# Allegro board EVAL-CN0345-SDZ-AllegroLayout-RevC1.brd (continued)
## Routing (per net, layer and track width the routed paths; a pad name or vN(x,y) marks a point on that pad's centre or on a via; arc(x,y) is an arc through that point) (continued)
GPIO2: length 43.5
  TOP w0.305: v1(127.64,13.97) 120.65,13.97 113.03,6.35 111.76,6.35 108.27,9.84 R21.2 ; P22.44 139.51,20.45 v1(140.02,20.95)
  BOTTOM w0.305: v1(127.64,13.97) 127.64,15.01 130.09,17.46 130.18,17.46 130.18,17.48 130.48,17.78 132.4,17.78 135.06,20.44 139.51,20.44 v1(140.02,20.95)
GPIO3: length 33.4
  TOP w0.305: v1(108.04,7.62) R19.2 ; P22.77 129.04,20.45 127.64,19.05 127.64,16.51 126.37,15.24 118.75,15.24 113.67,10.16 v1(111.44,10.16)
  BOTTOM w0.305: v1(108.04,7.62) 108.9,7.62 v1(111.44,10.16)
GPIO4: length 42.2
  TOP w0.305: v1(126.37,13.14) 121.73,13.14 113.67,5.08 107.38,5.08 107.06,5.4 R18.2 ; P22.45 140.08,19.86 v1(140.11,19.89)
  BOTTOM w0.305: v1(126.37,13.14) 127.85,13.14 128.59,13.88 128.59,14.92 130.81,17.14 132.72,17.14 135.42,19.85 139.35,19.85 139.38,19.89 v1(140.11,19.89)
GPIO5: length 35.1
  TOP w0.305: v1(108.27,3.17) R17.2 ; v1(112.71,7.62) 113.03,7.62 120.02,14.61 126.68,14.61 128.27,16.19 128.27,18.8 129.32,19.85 P22.76
  BOTTOM w0.305: v1(112.71,7.62) v1(108.27,3.17)
IN0A: length 14.4
  TOP w0.305: U2.19 47.27,25.04 46.36,24.13 43.82,24.13 41.12,26.83 39.26,26.83 38.2,27.89 C9.2 R9.2
IN0B: length 14.3
  TOP w0.305: U2.11 46.62,33.24 46.63,33.26 46.63,33.81 46.62,33.82 46.62,34.03 46.36,34.29 44.77,34.29 41.75,31.27 39.26,31.27 38.2,30.21 C8.2
  TOP w0.381: C8.2 R8.2
IN1A: length 15.2
  TOP w0.305: R10.2 C10.2 38.2,25.67 39.26,24.61 41.75,24.61 43.02,23.34 46.83,23.34 47.92,24.42 U2.20
IN1B: length 14.7
  TOP w0.305: C7.2 38.2,32.44 39.26,33.5 41.58,33.5 43.17,35.08 46.36,35.08 47.27,34.17 U2.10
  TOP w0.381: R7.2 C7.2
IN2A: length 16
  TOP w0.305: U2.21 48.57,23.8 47.15,22.38 39.26,22.38 38.2,23.44 C11.2 R11.2
IN2B: length 15.4
  TOP w0.305: U2.9 47.92,34.79 46.99,35.72 39.26,35.72 38.2,34.66 C6.2
  TOP w0.381: C6.2 R6.2
IN3A: length 17.8
  TOP w0.305: U2.22 49.22,23.41 45.97,20.16 39.26,20.16 38.2,21.22 C12.2 R12.2
IN3B: length 17.3
  TOP w0.305: C5.2 38.2,36.88 39.26,37.94 46.04,37.94 48.57,35.41 U2.8
  TOP w0.381: C5.2 R5.2
IN4A: length 19.5
  TOP w0.305: U2.23 49.87,23.2 44.61,17.94 39.26,17.94 38.2,19 C13.2 R13.2
IN4B: length 19.1
  TOP w0.305: C4.2 38.2,39.1 39.26,40.16 44.93,40.16 49.22,35.87 U2.7
  TOP w0.381: R4.2 C4.2
IN5A: length 21.3
  TOP w0.305: U2.24 50.52,22.9 43.34,15.72 39.26,15.72 38.2,16.78 C14.2 R14.2
IN5B: length 21.1
  TOP w0.305: U2.6 49.87,36.49 43.97,42.39 39.26,42.39 38.2,41.33 C3.2
  TOP w0.381: C3.2 R3.2
IN6A: length 23.2
  TOP w0.305: R15.2 C15.2 38.2,14.55 39.26,13.49 42.39,13.49 51.17,22.28 U2.25
IN6B: length 23
  TOP w0.305: U2.5 50.52,37.11 43.02,44.61 39.26,44.61 38.2,43.55 C2.2
  TOP w0.381: C2.2 R2.2
IN7A: length 25.1
  TOP w0.305: U2.26 51.82,21.66 41.43,11.27 39.26,11.27 38.2,12.33 C16.2 R16.2
IN7B: length 24.9
  TOP w0.305: U2.4 51.17,37.73 42.07,46.83 39.26,46.83 38.2,45.77 C1.2
  TOP w0.381: R1.2 C1.2
IN+: length 31
  TOP w0.305: U1.3 100.63,22.86 100.32,22.54
  TOP w0.635: 100.32,22.54 97.47,22.54 IN+.1 93.35,24.13 92.71,23.49 C28.1 88.68,23.49 C30.2 88.58,25.3 R32.2 ; R27.2 v1(90.17,32.54)
  BOTTOM w0.635: IN+.1 90.17,29.84 v1(90.17,32.54)
IN-: length 14.9
  TOP w0.635: IN-.1 88.48,17.68 R33.2 88.48,21.59 C30.1 88.68,21.59 C29.2 92.71,21.59 93.66,20.64 R29.1
MUX_ADDR0: length 79
  TOP w0.305: U2.17 v1(45.97,24.89)
  TOP w0.381: R19.1 R71.2 102.24,7.05 101.7,6.51 91.6,6.51 89.54,4.45 MUX_0.1 84.33,7.43 70.93,7.43 66.97,3.47 57.8,3.47 P6.2
  BOTTOM w0.305: P6.2 51.12,10.16 51.12,10.52 51.15,10.55 51.15,11.04 51.12,11.07 51.12,12.38 47.63,15.88 47.63,23.23 v1(45.97,24.89)
MUX_ADDR1: length 86.8
  TOP w0.305: U2.16 v1(45.32,27.68) ; R18.1 R70.2
  TOP w0.381: P5.2 51.12,6.35 51.12,3.08 51.5,2.7 67.47,2.7 71.44,6.67 77.79,6.67 MUX_1.1 81.6,2.86 91.44,2.86 92.87,4.29 101.82,4.29 102.24,4.7 R70.2
  BOTTOM w0.305: P5.2 47.31,10.16 47.31,10.52 47.34,10.55 47.34,11.04 47.31,11.07 47.31,13.65 46.04,14.92 46.04,21.91 45.25,22.7 45.25,25.19 45.32,25.26 v1(45.32,27.68)
MUX_ADDR2: length 86.6
  TOP w0.305: U2.15 44.67,25.46 v1(44.13,24.92)
  TOP w0.381: P4.2 47.31,6.35 47.31,2.44 47.69,2.06 68.26,2.06 70.64,4.45 MUX_2.1 74.61,4.45 77.47,1.59 101.35,1.59 102.24,2.48 R69.2 R17.1
  BOTTOM w0.305: v1(44.13,24.92) 44.13,21.27 43.47,20.61 43.47,10.19 P4.2
MUX_EN: length 26
  TOP w0.305: U2.18 v1(46.62,27.68)
  BOTTOM w0.305: P26.2 46.67,41.91 47.63,40.96 47.63,30.8 46.62,29.79 v1(46.62,27.68)
N15VA: length 16.9
  TOP w0.305: v1(67,32.23) 66.72,31.95 U3.6
  TOP w0.508: 71.76,50.42 P21.3 ; P21.3 70.42,51.75 ; P21.3 71.76,53.09
  L3_POWER w0.508: 61.91,17.78 P12.2 ; P12.2 63.18,16.51 ; P12.2 63.18,19.05 ; P7.2 58.74,19.05 ; P7.2 60.01,17.78 ; P7.2 58.74,16.51 ; P21.3 71.76,53.09 ; P21.3 71.76,50.42 ; P21.3 70.42,51.75
PD: length 90.7
  TOP w0.305: P23.3 92.71,44.77 v1(96.52,48.58) ; v1(127.32,12.38) v1(123.19,12.38) ; v1(140.02,17.78) 139.75,18.05 P22.48
  BOTTOM w0.305: v1(127.32,12.38) 128.27,12.38 130.49,14.61 133.03,14.61 136.21,17.78 v1(140.02,17.78) ; v1(96.52,48.58) 117.49,48.58 120.02,46.05 120.02,37.78 120.65,37.15 120.65,32.38 119.38,31.11 119.38,16.19 v1(123.19,12.38)
SCLK: length 20.1
  TOP w0.305: U16.4 121.3,33.03 SCLK.1 111.13,22.86 U1.8
SDI: length 18
  TOP w0.305: P18.2 115.57,34.61 115.57,31.75 SDI.1 110.81,26.99 110.81,24.13 110.04,23.36 U1.9
SDO: length 30.3
  TOP w0.305: P22.91 126.8,28.85 125.91,27.97 124.24,27.97 124.22,27.94 121.92,27.94 121.6,27.62 120.33,27.62 SDO.1 110.99,22.36 U1.7
SDP_3P3V: length 51.7
  TOP w0.305: U12.3 123.22,7.65 122.87,7.3 v1(122.87,6.99) 122.87,6.34 122.57,6.03 121.67,6.03 R65.2 ; U12.8 127.29,9.09 127.32,9.12 127.32,9.84
  TOP w0.381: P22.116 131.23,43.85 130.87,43.5
  TOP w0.635: 127.32,9.84 125.57,11.59 v1(124.62,11.59) ; 130.87,43.5 129.86,43.5 v1(129.54,43.18)
  BOTTOM w0.305: v1(122.87,6.99) 122.87,10.16 123.51,10.8 123.83,10.8 v1(124.62,11.59)
  BOTTOM w0.635: v1(124.62,11.59) 124.62,12.48 124.78,12.64 124.78,13.97 127.32,16.51 127.32,23.16 129.98,25.82 129.98,27.5 129.54,27.94 v1(129.54,43.18)
SPORT_DT0: length 22.4
  TOP w0.305: P18.3 120.14,35.56 120.78,34.92 v1(128.59,34.92) ; v1(128.78,26.67) 129.16,27.05 P22.88
  BOTTOM w0.305: v1(128.59,34.92) 128.59,34.2 128.78,34.01 v1(128.78,26.67)
SPORT_RFS: length 10.7
  TOP w0.305: P22.90 126.99,28.25 126.15,27.41 124.47,27.41 123.75,26.68 U15.4
SPORT_RSCLK: length 22.3
  TOP w0.305: U14.4 122.37,20.33 122.35,20.32 v1(121.29,20.32) ; P22.92 126.61,29.45 125.73,28.57 v1(121.29,28.57)
  BOTTOM w0.305: v1(121.29,28.57) 120.65,27.94 120.65,20.95 v1(121.29,20.32)
SPORT_TSCLK: length 22
  TOP w0.305: P22.87 129.64,26.45 128.91,25.72 v1(127.95,25.72) 126.68,24.45 126.68,20.95 125.49,19.76 125.3,19.76 125.23,19.68 U14.2 ; U16.1 125.28,31.74 125.3,31.75 v1(127.64,31.75)
  BOTTOM w0.305: v1(127.95,25.72) 127.95,30.71 127.64,31.03 v1(127.64,31.75)
SW0: length 41.8
  TOP w0.305: R8.1 25.4,30.16 25.08,30.48 S1.8 22.23,30.48 20.96,31.75 13.97,31.75 6.35,39.37 6.35,46.62 P1.8
SW1: length 42.9
  TOP w0.305: R7.1 25.72,32.38 25.08,33.02 S1.7 22.23,33.02 20.96,34.29 13.97,34.29 7.62,40.64 7.62,48.85 P1.7
SW2: length 44.4
  TOP w0.305: R6.1 25.08,34.61 S1.6 22.23,35.56 20.96,36.83 13.34,36.83 8.89,41.27 8.89,51.08 P1.6
SW3: length 45.8
  TOP w0.305: R5.1 27.94,36.83 26.67,38.1 S1.5 22.23,38.1 20.96,39.37 12.7,39.37 10.16,41.91 10.16,53.31 P1.5
SW4: length 46.9
  TOP w0.305: P1.4 11.43,55.54 11.43,43.18 12.7,41.91 20.96,41.91 22.23,40.64 S1.4 26.67,40.64 28.26,39.05 R4.1
SW5: length 47.6
  TOP w0.305: P1.3 12.7,57.77 12.7,45.09 13.34,44.45 20.96,44.45 22.23,43.18 S1.3 27.31,43.18 29.21,41.27 R3.1
SW6: length 43.7
  TOP w0.305: R2.1 30.16,43.5 27.94,45.72 S1.2 23.18,45.72 20.96,47.94 20.96,53.01 P1.2
SW7: length 44.2
  TOP w0.305: P1.1 24.13,53.34 S1.1 27.94,48.26 30.48,45.72 R1.1
UNNAMED_1_AD7982V2_I124_INNEG: length 5.5
  TOP w0.305: R30.1 99.7,20.68 100.28,21.26 100.32,21.26 101.42,22.36 U1.4
  TOP w0.635: R29.2 R30.1
UNNAMED_1_AD7982V2_I124_VDD: length 19.1
  TOP w0.305: C32.2 100.88,23.36 U1.2
  TOP w1.016: C32.2 99.34,23.91 v1(95.28,27.97)
  BOTTOM w1.016: 96.2,37.46 96.2,33.34 95.28,32.42 v1(95.28,27.97)
UNNAMED_1_AD7982V2_I124_VIO: length 13.3
  TOP w0.305: 107.73,25.15 107.79,25.09 107.79,24.19 107.45,23.86 U1.10
  TOP w0.381: C33.1 107.73,25.15
  TOP w0.635: C33.1 107.73,27.05 107.53,27.25 107.53,33.55 P17.2
UNNAMED_1_AD8251_I135_: length 7.9
  TOP w0.305: 64.26,26.67 64.32,26.72 U3.1
  TOP w0.635: R23.1 59.37,27.94 PGIA-.1 64.26,26.67
UNNAMED_1_AD8251_I135__1: length 7.8
  TOP w0.305: 64.26,31.11 64.32,31.06 U3.10
  TOP w0.635: 64.26,31.11 PGIA+.1 59.69,30.16 R24.1
UNNAMED_1_AD8251_I135__2: length 9.2
  TOP w0.305: C23.1 65.41,25.24 65.72,25.56 U3.3
  TOP w1.016: C23.1 C22.1 65.41,20.18 65.72,19.86 P12.1
UNNAMED_1_AD8251_I135__3: length 10.4
  TOP w0.305: U3.8 65.72,32.38 65.41,32.7
  TOP w0.635: C19.2 65.41,33.66 65.41,32.7
  TOP w1.016: P13.2 C20.2 C19.2
UNNAMED_1_AD8251_I135_OUT: length 3.8
  TOP w0.305: U3.7 66.22,30.15 66.53,29.84 67.31,29.84
  TOP w0.635: R26.1 67.31,29.84
UNNAMED_1_AD8475V2_I91_NEGIN04X: length 8.4
  TOP w0.305: R28.2 74.51,26.14 76.84,23.81 76.84,23.49 77.97,22.36 U5.2
UNNAMED_1_AD8475V2_I91_NEGIN08X: length 2.7
  TOP w0.305: U5.1 79.1,21.86 78.32,21.08 C25.2
UNNAMED_1_AD8475V2_I91_NEGVS: length 2.9
  TOP w0.305: U5.8 P24.1
UNNAMED_1_AD8475V2_I91_POSIN08X: length 2.6
  TOP w0.305: C25.1 76.62,20.84 75.6,21.86 U5.10
UNNAMED_1_AD8475V2_I91_POSVS: length 14.8
  TOP w0.305: U5.3 78.35,22.86 77.61,23.61 77.61,24.25 77.15,24.7 C26.2
  TOP w0.635: P15.2 75.88,32.7 75.88,26.14 76.52,25.5 C26.2
UNNAMED_1_AD8475V2_I91_VOCM: length 7
  TOP w0.305: VOCM.1 81.53,23.18 81.35,23.36 U5.4 78.56,23.36 78.32,23.6 78.32,24.03 79.38,25.08 R68.1
UNNAMED_1_ADA48051_I112_: length 18.6
  TOP w0.635: U4.4 85.09,39.05 84.61,39.53 84.61,41.12 83.82,41.91 v1(77.79,41.91) 76.2,41.91 75.41,41.12 75.41,40.43 RN1.2 RN1.1 ; RN1.13 v1(77.79,44.13)
  BOTTOM w0.635: v1(77.79,44.13) v1(77.79,41.91)
UNNAMED_1_ADA48051_I112__1: length 13.9
  TOP w0.635: RN1.12 RN1.11 RN1.10 81.6,44.12 81.9,43.81 85.73,43.81 88.19,41.35 U4.3
UNNAMED_1_ADA48051_I112__2: length 10.6
  TOP w0.635: U4.2 89.22,38.1 89.67,38.55 89.68,38.56 89.68,42.08 UNK-VS.1
  TOP w1.016: UNK-VS.1 P14.1
UNNAMED_1_ADA48051_I112__3: length 5.8
  TOP w0.635: U4.6 85.41,37.15 84.96,36.7 84.96,35.16 C21.1 83.5,34.92 82.87,34.29 P11.2
UNNAMED_1_ADA48051_I112_DISABLE: length 9
  TOP w0.635: U4.5 v1(84.77,38.1)
  BOTTOM w0.635: v1(84.77,38.1) P23.2
UNNAMED_1_ADA48051_I112_VOUT: length 22.3
  TOP w0.635: R27.1 89.85,37.15 U4.1 87.57,37.15 87,37.73 87,40.64 84.77,42.86 76.5,42.86 75.25,44.12 RN1.15 RN1.16
UNNAMED_1_ADG1207_I45_DA: length 3.9
  TOP w0.381: U2.28 53.12,27.4 53.66,27.94 R23.2
UNNAMED_1_ADG1207_I45_DB: length 4.7
  TOP w0.381: R24.2 53.33,30.16 52.47,31.02 U2.2
UNNAMED_1_ADG1207_I45_VDD: length 9.2
  TOP w0.381: C18.1 53.12,33.72 53.12,33.71 U2.1
  TOP w1.016: C18.1 53.12,39.88 53.34,40.09 P8.2
UNNAMED_1_ADG1207_I45_VSS: length 10.7
  TOP w0.305: U2.27 52.47,25.32 52.81,24.98 52.81,23.81 C17.1
  TOP w0.635: P7.1 52.81,21.17 52.81,23.81
UNNAMED_1_CAP_I95_N2: length 13.6
  TOP w0.635: R68.2 79.38,27.77 80.28,28.68 C27.2 81.34,28.68 81.56,28.89 R31.2 R34.1
UNNAMED_1_CN9P_I241_N1: length 35.7
  TOP w0.305: P25.1 5.72,38.73 5.72,37.46 15.24,27.94 R9.1
UNNAMED_1_CN9P_I241_N2: length 34.4
  TOP w0.305: R10.1 15.23,25.72 P25.2
UNNAMED_1_CN9P_I241_N3: length 33.9
  TOP w0.305: R11.1 13.96,23.49 P25.3
UNNAMED_1_CN9P_I241_N4: length 33.4
  TOP w0.305: P25.4 12.68,21.27 R12.1
UNNAMED_1_CN9P_I241_N5: length 32.8
  TOP w0.305: R13.1 11.4,19.05 P25.5
UNNAMED_1_CN9P_I241_N6: length 32.3
  TOP w0.305: P25.6 10.12,16.83 R14.1
UNNAMED_1_CN9P_I241_N7: length 31.8
  TOP w0.305: P25.7 8.85,14.61 R15.1
UNNAMED_1_CN9P_I241_N8: length 31.2
  TOP w0.305: R16.1 7.57,12.38 P25.8
UNNAMED_1_RES_I104_N1: length 27.4
  TOP w0.305: U5.6 74.25,23.86 73.98,24.13 71.12,24.13 70.8,23.81 70.8,18.08 71.11,17.78 79.69,17.78 81.6,19.68 R33.1
UNNAMED_1_RES_I109_N1: length 7.8
  TOP w0.305: U5.5 80.56,23.86 82.1,25.4 R32.1
UNNAMED_1_RES_I214_N2: length 4.5
  TOP w0.635: R20.2 74.35,36.73 75.19,37.57 75.19,37.62 76.52,38.95 RN1.3
UNNAMED_1_RES_I215_N2: length 2.5
  TOP w0.635: RN1.9 82.87,46.79 82.77,46.89 R25.2
UNNAMED_1_RES_I218_N1: length 19.4
  TOP w0.635: R67.1 88.9,31.11 87.63,32.38 81.6,32.38 80.01,33.97 80.01,37.46 79.06,38.42 RN1.5
UNNAMED_1_RESNET16P8R_I207_N1: length 1.3
  TOP w0.635: RN1.7 RN1.8
UNNAMED_1_RESNET16P8R_I208_N1: length 11.2
  TOP w0.635: RN1.14 v1(76.52,46.99) ; v1(77.79,39.05) RN1.4
  BOTTOM w0.635: v1(76.52,46.99) 76.52,40.32 v1(77.79,39.05)
UNNAMED_2_AD8541ART_I251__1: length 3.7
  TOP w0.508: U9.1 102.83,32.66 101.96,32.66 101.6,33.02 101.6,33.62 100.61,34.61 U9.4
UNNAMED_2_ADP121_I85_EN: length 3.5
  TOP w0.635: U11.3 89.54,69.21 89.64,69.32 91.61,69.32
UNNAMED_2_ADP5070_I245_COMP1: length 3.1
  TOP w0.305: 75.57,84.46 75.57,83.87 74.02,82.33 U6.6
UNNAMED_2_ADP5070_I245_COMP2: length 3.4
  TOP w0.305: 70.49,84.46 70.49,83.5 70.8,83.19 71.44,83.19 72.03,82.6 U6.10
UNNAMED_2_ADP5070_I245_EN1: length 8.3
  TOP w0.305: R39.2 R37.2 74.61,83.82 73.53,82.73 U6.7
UNNAMED_2_ADP5070_I245_EN2: length 8.3
  TOP w0.305: U6.9 72.52,83 73.34,83.82 73.34,87 73.03,87.31 R38.2 R41.1
UNNAMED_2_ADP5070_I245_FB1: length 4.3
  TOP w0.305: U6.5 76.09,81.01 76.45,80.65 R52.1 77.25,81.5 77.15,81.6 R44.2
UNNAMED_2_ADP5070_I245_FB2: length 5
  TOP w0.305: U6.11 70.53,81.01 70.17,81.37 70.17,82.3 69.6,82.87 R47.1 R49.1
UNNAMED_2_ADP5070_I245_PVIN1: length 24.5
  TOP w0.635: 63.5,78.42 63.5,85.09 67.95,89.54 R41.2 71.44,91.12 71.76,91.44 75.57,91.44 76.2,90.81 R39.1
UNNAMED_2_ADP5070_I245_SW2: length 1.5
  TOP w0.305: U6.18 73.03,76.52
UNNAMED_2_ADP5070_I245_VREF: length 4.6
  TOP w0.305: U6.12 70.05,80.51 69.91,80.65 69.43,80.65 69.1,80.98 C48.1 69.1,81.1 67.63,82.58 R47.2
UNNAMED_2_ADP5070_I245_VREG: length 2.2
  TOP w0.305: C36.2 69.88,79.51 U6.14
UNNAMED_2_ADP7104_I106_EN: length 4.5
  TOP w0.305: R43.2 91.12,86.36 ; 91.12,86.36 91.12,87.69 91.38,87.95 R48.2 ; 91.12,86.36 91.64,85.84 U7.5
UNNAMED_2_ADP7104_I106_PG: length 2
  TOP w0.305: R54.2 90.87,84.77 90.94,84.84 U7.7
UNNAMED_2_ADP7104_I106_SENSE: length 8.1
  TOP w0.305: R54.1 v1(88.9,84.14)
  BOTTOM w0.305: v1(88.9,84.14) 89.76,83.27 94.93,83.27 95.16,83.5 v1(95.89,83.5)
UNNAMED_2_ADP7104_I106_VIN: length 5.7
  TOP w0.305: R43.1 87.95,86.36 87.63,86.04 87.63,83.3 88.16,82.77 R42.2
UNNAMED_2_ADR43X_I253_COMP: length 3.5
  TOP w0.635: R40.1 101.28,46.14 U8.7
UNNAMED_2_ADR43X_I253_VOUT: length 2.9
  TOP w0.635: U8.6 C39.2
UNNAMED_2_CAP_I115_N1: length 2.2
  TOP w1.016: C37.1 R40.2
UNNAMED_2_CAP_I216_N2: length 17.9
  TOP w0.381: R52.2 v1(80.01,80.65)
  BOTTOM w0.381: v1(80.01,80.65) v1(80.01,63.82)
UNNAMED_2_CAP_I221_N1: length 1.6
  TOP w0.305: R45.2 C46.1
UNNAMED_2_CAP_I228_N1: length 22.7
  TOP w0.381: R49.2 v1(66.68,84.46)
  BOTTOM w0.381: v1(64.77,63.5) 64.77,82.55 v1(66.68,84.46)
UNNAMED_2_CAP_I234_N1: length 1.6
  TOP w0.305: R46.2 C47.1
UNNAMED_2_CAP_I257_N2: length 6.4
  TOP w0.508: UNK+15V.1 85.09,57.47 ; UNK+15V.1 85.09,54.29 ; UNK+15V.1 83.5,55.88 ; UNK+15V.1 86.68,55.88
UNNAMED_2_CAP_I258_N2: length 6.4
  TOP w0.508: UNK-15V.1 63.18,55.88 ; UNK-15V.1 61.6,54.29 ; UNK-15V.1 61.6,57.47 ; UNK-15V.1 60.01,55.88
UNNAMED_2_CN2P_I119_N1: length 54.7
  TOP w2.54: P3.1 103.51,84.77 107.21,81.07 107.21,41.78 105.41,39.98 P2.3
UNNAMED_2_DIOLED_I248_P: length 5.7
  TOP w0.508: POWER.A R35.1
UNNAMED_3_CMOSNC7S04_I15_Y: length 19.1
  TOP w0.305: v1(127.83,33.02) 127.11,33.02 126.47,32.38 U16.2 ; U13.4 122.53,40.92 122.56,40.95 122.56,41.59 122.87,41.91 v1(127.32,41.91)
  BOTTOM w0.305: v1(127.32,41.91) 128.27,40.96 128.27,36.51 127.64,35.88 127.64,33.97 127.83,33.78 v1(127.83,33.02)
UNNAMED_3_CN120PV4_I1_EEPROMA0: length 22.7
  TOP w0.305: v1(124.14,9.53) 124.14,9.12 124.2,9.06 U12.1 122.39,8.65 121.59,9.45 R64.2 ; P22.56 v1(140.01,13.25)
  BOTTOM w0.305: 124.65,10.04 v1(124.14,9.53)
  BOTTOM w0.381: v1(140.01,13.25) 131.04,13.25 127.83,10.04 124.65,10.04
UNNAMED_3_CN120PV4_I1_SCL0: length 19.6
  TOP w0.305: v1(129.22,18.73) 129.22,8.57 128.3,7.65 127.3,7.65 U12.6 ; P22.79 129.6,21.65 v1(129.22,22.03)
  BOTTOM w0.305: v1(129.22,22.03) v1(129.22,18.73)
UNNAMED_3_CN120PV4_I1_SDA0: length 20.3
  TOP w0.305: U12.5 128.75,7.15 130.18,8.57 v1(130.18,19.05) ; v1(130.18,22.6) 130.52,22.25 P22.80
  BOTTOM w0.305: v1(130.18,22.6) v1(130.18,19.05)
UNNAMED_3_IC24XX32A_I2_A1: length 4.9
  TOP w0.305: U12.2 122.94,8.15 122.39,7.6 R65.1 R66.2
VREF: length 8.4
  TOP w0.508: 99.7,27.3 VREF.1
  TOP w0.635: VREF.1 101.75,28.89 101.85,28.99 R53.2
  TOP w1.016: VREF.1 97.47,28.89 96.52,29.84

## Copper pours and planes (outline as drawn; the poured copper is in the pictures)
2.5VA on TOP (solid shape): outline of 98 points within 88.9,53.02 93.98,60.01
2.5VA on BOTTOM (solid shape): 94.93,56.83 94.93,47.94 96.52,46.35 96.52,42.55 97.16,41.91 97.16,39.37 94.93,39.37 94.93,43.18 91.44,46.67 91.44,49.21 88.9,51.75 88.9,57.78 93.98,57.78
5VA on TOP (solid shape): outline of 94 points within 94.93,60.96 99.38,78.42
5VA on L3_POWER: 75.88,28.57 75.88,38.73 80.96,38.73 94.93,52.7 94.93,64.45 95.89,65.41 98.74,65.41 100.65,63.5 129.54,63.5 132.72,60.32 132.72,50.8 135.89,47.62 140.44,47.62 140.44,44.13 133.99,44.13 129.86,48.26 129.86,57.78 127.64,60.01 112.71,60.01 109.22,56.52 109.22,53.34 108.27,52.39 102.24,52.39 97.16,47.31 97.16,34.92 99.06,33.02 99.06,30.16 96.2,30.16 90.81,35.56 88.58,35.56 81.6,28.57
AGND on TOP: 140.97,94.62 0.95,94.62 0.95,0.64 140.97,0.64 ; 4 cut-outs
AGND on BOTTOM: 140.65,93.98 0.95,93.98 0.95,1.27 140.65,1.27
AGND on L2_GND: 1.27,1.27 1.27,93.98 140.44,93.98 140.44,1.27 ; 2 cut-outs
AGND on L3_POWER: 1.27,1.27 1.27,93.98 140.44,93.98 140.44,1.27 ; 2 cut-outs
P15VA on TOP (solid shape): 102.24,58.74 102.24,55 101.99,55 101.99,52.39 100.57,52.39 100.57,55 100.33,55 100.33,58.1 100.01,58.42 98.43,58.42 97.16,57.15 97.16,51.44 94.93,49.21 76.2,49.21 75.57,49.85 75.57,50.55 78.04,50.55 78.04,52.96 75.57,52.96 75.57,53.66 78.42,53.66 78.74,53.98 78.74,57.09 81.03,57.09 81.6,56.52 81.6,53.34 83.19,51.75 93.35,51.75 94.62,53.02 94.62,58.42 96.2,60.01 100.97,60.01
P15VA on BOTTOM (solid shape): outline of 208 points within 50.8,41.91 78.74,53.98
VIN on TOP (solid shape): 87,89.85 87,80.96 84.46,80.96 84.46,88.27 80.33,92.39 65.72,92.39 60.33,87 56.83,87 56.21,87.62 60.72,87.62 60.72,90.92 57.8,90.92 57.8,87.62 56.21,87.62 55.88,87.95 55.88,91.12 58.74,93.98 82.87,93.98
VIN on TOP (solid shape): outline of 205 points within 39.05,73.34 61.28,91.44
3P3V on TOP (solid shape): outline of 123 points within 107.95,33.66 121.29,66.04
3P3V on L3_POWER: 112.71,58.42 112.71,53.66 120.33,46.04 120.33,13.97 114.62,8.25 34.29,8.25 34.29,3.17 125.41,3.17 127.64,5.4 127.64,46.67 115.89,58.42
N15VA on TOP (solid shape): 69.85,56.52 69.85,54.29 70.49,53.66 72.71,53.66 72.71,52.96 72.4,52.78 72.33,52.81 70.55,51.75 72.33,50.69 72.4,50.73 72.71,50.54 72.71,50.16 71.91,49.37 65.72,49.37 65.72,56.83 69.53,56.83
N15VA on L3_POWER (solid shape): outline of 631 points within 57.15,15.88 73.03,53.98
UNNAMED_2_AD8541ART_I251_ on TOP (solid shape): 103.82,34.61 101.92,34.61 101.92,38.73 103.82,38.73
UNNAMED_2_AD8541ART_I251__1 on TOP (solid shape): 103.82,30.16 101.92,30.16 101.92,33.02 103.82,33.02
UNNAMED_2_ADP121_I85_EN on TOP (solid shape): 94.3,66.99 91.12,66.99 91.12,73.03 94.3,73.03
UNNAMED_2_ADP121_I85_VOUT on TOP (solid shape): 93.66,60.64 90.81,60.64 90.81,61.59 91.12,61.91 91.12,66.36 93.66,66.36
UNNAMED_2_ADP124_I107_EN on TOP (solid shape): 113.03,70.17 113.98,69.22 113.98,69.01 112.04,69.01 112.04,68.17 113.98,68.17 113.98,67.31 113.67,66.99 112.71,66.99 112.71,62.87 110.81,62.87 110.81,72.39 113.03,72.39
UNNAMED_2_ADP124_I107_VOUT1 on TOP (solid shape): 121.29,72.07 121.29,66.68 118.11,66.68 117.79,66.99 116.52,66.99 116.52,68.82 118.47,68.82 118.47,68.9 118.75,68.9 118.75,70.48 117.48,70.48 117.48,73.03 120.33,73.03
UNNAMED_2_ADP5070_I245_INBK on TOP (solid shape): 83.19,79.06 83.19,77.15 77.47,77.15 76.2,78.42 74.93,78.42 74.61,78.74 74.61,79.1 76.13,79.1 76.15,79.12 76.2,79.12 76.47,79.19 76.68,79.38 82.87,79.38
UNNAMED_2_ADP5070_I245_PVIN1 on TOP (solid shape): 71.44,78.42 72.62,78.42 72.62,77.38 72.39,77.15 72.39,74.93 72.07,74.61 65.41,74.61 64.14,75.88 62.13,75.88 62.13,76.15 61.53,76.15 61.53,76.45 61.02,76.45 61.02,76.15 60.43,76.15 60.43,75.88 58.74,75.88 58.74,78.11 59.06,78.42 65.09,78.42 66.04,77.47 69.53,77.47 70.17,78.11 70.17,79.06 71.44,79.06
UNNAMED_2_ADP5070_I245_SW1 on TOP (solid shape): 74.77,78.04 75.95,78.04 77.47,76.52 77.47,76.2 77.79,75.88 83.19,75.88 83.19,72.39 82.55,71.76 79.38,71.76 76.2,74.93 76.2,76.52 75.57,77.15 74.61,77.15 73.98,77.79 73.98,78.42 74.39,78.42
UNNAMED_2_ADP5070_I245_SW2 on TOP (solid shape): 73.34,76.89 73.34,68.26 70.8,68.26 70.8,69.53 70.17,70.17 68.26,70.17 67.95,70.48 67.95,73.34 68.26,73.66 72.07,73.66 72.39,73.98 72.39,74.31 72.68,74.31 72.68,74.68 72.77,74.77 72.77,76.99 73.01,77.23
UNNAMED_2_ADP7104_I106_SENSE on TOP (solid shape): 98.43,84.77 98.43,79.06 95.89,79.06 95.89,82.87 94.77,83.98 94.77,84.93 95.52,84.93 95.7,84.97 95.85,85.09 98.11,85.09
UNNAMED_2_ADP7104_I106_VIN on TOP (solid shape): 92.56,83.98 91.54,82.97 91.49,82.97 91.49,82.92 91.12,82.55 91.12,79.06 87.63,79.06 87.63,83.5 90.17,83.5 90.78,84.11 90.87,84.11 90.87,84.2 91.03,84.37 91.04,84.37 91.1,84.43 92.41,84.43 92.48,84.44 92.54,84.46 92.56,84.46
UNNAMED_2_ADR43X_I253_VOUT on TOP (solid shape): 100.65,44.45 100.97,44.13 102.24,44.13 102.55,43.81 102.55,42.55 100.97,42.55 100.97,39.05 101.28,38.73 101.28,36.83 99.38,36.83 99.38,46.67 100.65,46.67
UNNAMED_2_CAP_I214_N2 on TOP (solid shape): 83.19,70.8 83.19,66.36 79.06,66.36 77.79,65.09 76.52,65.09 76.52,67.31 77.15,67.95 78.42,67.95 78.74,68.26 78.74,71.12 82.87,71.12
UNNAMED_2_CAP_I216_N2 on TOP (solid shape): 83.5,62.55 82.87,61.91 79.06,61.91 78.74,61.59 78.74,60.96 77.15,60.96 77.15,63.5 79.38,65.72 83.5,65.72
UNNAMED_2_CAP_I228_N1 on TOP (solid shape): 68.26,64.45 70.17,64.45 70.17,60.96 68.58,60.96 67.63,61.91 63.18,61.91 62.87,62.23 62.87,65.72 66.99,65.72
UNNAMED_2_CAP_I257_N2 on TOP (solid shape): outline of 101 points within 77.15,53.02 87.95,61.28
UNNAMED_2_CAP_I258_N2 on TOP (solid shape): outline of 102 points within 58.74,53.02 70.17,61.28
UNNAMED_2_CAP_I264_N2 on TOP (solid shape): 70.17,65.09 68.58,65.09 67.31,66.36 62.87,66.36 62.87,68.9 63.5,69.53 70.17,69.53
VREF on TOP (solid shape): 97.16,29.84 99.7,29.84 99.7,27.62 97.79,27.62 96.52,28.89 94.62,28.89 93.98,28.26 92.71,28.26 92.71,31.75 95.25,31.75
VREF on TOP (solid shape): 100.97,29.53 103.82,29.53 103.82,24.45 103.19,23.81 101.6,23.81 101.6,26.35 100.33,27.62 99.06,27.62 98.43,28.26 98.43,29.53 99.06,30.16 100.33,30.16

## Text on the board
Ref Des/Silkscreen Top: C7- | C6- | C5- | C4- | C3- | C2- | C1- | C0- | GND | C0+ | C1+ | C2+ | C3+ | C4+ | C5+ | C6+ | C7+ | DIFF | SE | EN | DIS | HLM: 08-037251 Rev-C | AGND | +6V | VREF | EVAL-CN0345-SDZ | 08-      -03
DIMENSION: NOTES: | 1. THE BOARD SIZE MAY VARY TO COMPENSATE THE COMPONENTS DENSITY OF THE CIRCUIT. | 2. THE BOARD MAY EXTEND TO THE RIGHT AND LOWER PORTION IF THERE IS A NEED TO CHANGE THE BOARD SIZE. | 3. J1 CONNECTOR LOCATION IS FIXED WITH REFERENCE TO THE DISTANCE ON BOARD EDGE ON THE UPPER LEFT PORTION.
PAGE_OUTLINE: T SCHMITT | May 15 | n/a | N/A | CFTL BOARD
User.5: L2 GND | 08-      -07
User.6: L3 GND | 08-      -08
User.7: ROHS COMPLIANCE NOTE; | HOMOGENOUS MATERIAL IN THIS BOARD SHALL BE COMPLIANT | THE EU ROHS DIRECTIVE 2002/95/EC
User.11: L4 PWR | 08-      -09
User.12: 08-      -08 | L3 PWR
User.17: L6 PWR | 08-      -11
User.18: L7 GND | 08-      -12
User.25: FIGURE | SIZE | 12.0 | 35.0 | 40.0 | 45.0 | 50.0 | 60.0 | 63.0 | 28.0 | 43.0 | 71.0 | 125.0 | PLATED | NON-PLATED | FINISHED HOLES IN MILS | ALL UNITS ARE IN MILS | QTY | 282 | 24 | 20 | 30 | 2 | 27 | 1 | 5 | TOLERANCE/NOTES
